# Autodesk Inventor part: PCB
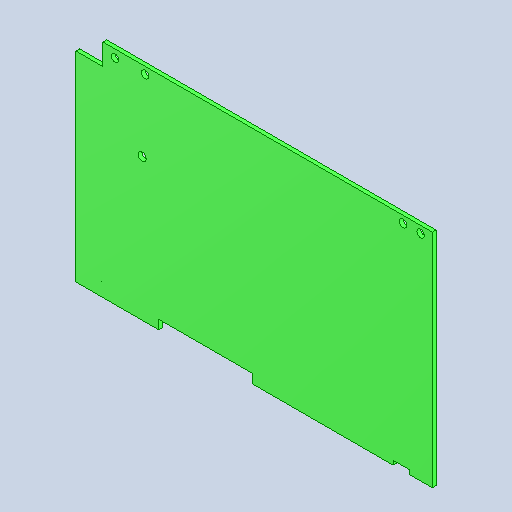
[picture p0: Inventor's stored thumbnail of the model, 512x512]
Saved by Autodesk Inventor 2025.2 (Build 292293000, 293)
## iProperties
Created: 2025-04
Part Number: PCB
Material: Generic
Description: NOT SPECIFIED
Document SubType Name: Modeling
Designer: BennF
Density: 1 g/cm^3
Appearance: Default
Author: BennF
Revision Number: 4LAST_VERSION
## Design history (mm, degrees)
feature "Base1"
body "Solid1"
